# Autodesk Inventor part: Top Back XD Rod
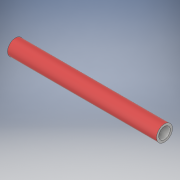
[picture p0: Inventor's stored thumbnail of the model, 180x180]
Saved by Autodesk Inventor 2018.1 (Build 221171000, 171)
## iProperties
Created: 2018-06
Part Number: Top Back XD Rod
Material: Generic
Document SubType Name: Modeling
Designer: Ryan
Density: 1 g/cm^3
Appearance: Default
Author: Ryan
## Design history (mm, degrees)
derived "Assembly3 Part out.iam"
sketch "Sketch1"
  geometry: L1 (-38.527, 77.015)-(136.232, 77.015); L2 (136.232, 77.015)-(136.232, -217.058); L3 (136.232, -217.058)-(-38.527, -217.058); L4 (-38.527, -217.058)-(-38.527, 77.015); 1 further point
  constraints: 8 end point, 2 parallel, 1 horizontal, 1 perpendicular
extrude "Extrusion1" cut sketch "Sketch1" distance "d1" = 25.4; taper "d2" = 0 deg
workplane "Work Plane2"
  workplane "Work Plane1"
workpoint "Work Point1"
workplane "Work Plane3"
workplane "Work Plane4"
workplane "Work Plane5"
workplane "Work Plane6"
workplane "Work Plane7"
workplane "Work Plane8"
workplane "Work Plane9"
workplane "Work Plane10"
workplane "Work Plane11"
workplane "Work Plane12"
sketch "Sketch2"
  geometry: L1 (227.789, 28.997)-(-104.46, 28.997); L2 (-104.46, 28.997)-(-104.46, -117.244); L3 (-104.46, -117.244)-(227.789, -117.244); L4 (227.789, -117.244)-(227.789, 28.997); 1 further point
  constraints: 8 end point, 2 parallel, 1 horizontal, 1 perpendicular
extrude "Extrusion2" cut sketch "Sketch2" distance "d10" = 169.8625; taper "d11" = 0 deg
sketch "Sketch3"
  geometry: L1 (244.466, 43.749)-(-96.122, 43.749); L2 (-96.122, 43.749)-(-96.122, -113.396); L3 (-96.122, -113.396)-(244.466, -113.396); L4 (244.466, -113.396)-(244.466, 43.749); 1 further point
  constraints: 8 end point, 2 parallel, 1 horizontal, 1 perpendicular
extrude "Extrusion3" cut sketch "Sketch3" distance "d12" = 169.8625; taper "d13" = 0 deg
sketch "Sketch4"
  geometry: L1 (228.431, 30.28)-(156.593, 30.28); L2 (156.593, 30.28)-(156.593, -87.098); L3 (156.593, -87.098)-(228.431, -87.098); L4 (228.431, -87.098)-(228.431, 30.28); L5 (-98.688, 23.865)-(-20.436, 23.865); L6 (-20.436, 23.865)-(-20.436, -58.235); L7 (-20.436, -58.235)-(-98.688, -58.235); L8 (-98.688, -58.235)-(-98.688, 23.865); 1 further point
  constraints: 16 end point, 4 parallel, 2 horizontal, 2 perpendicular
extrude "Extrusion4" cut sketch "Sketch4" distance "d14" = 169.8625; taper "d15" = 0 deg
sketch "Sketch5"
  geometry: L1 (189.305, 53.37)-(41.781, 53.37); L2 (41.781, 53.37)-(41.781, -120.451); L3 (41.781, -120.451)-(189.305, -120.451); L4 (189.305, -120.451)-(189.305, 53.37); 1 further point
  constraints: 8 end point, 2 parallel, 1 horizontal, 1 perpendicular
extrude "Extrusion5" cut sketch "Sketch5" distance "d16" = 201.6125; taper "d17" = 0 deg
sketch "Sketch6"
  geometry: C1 r 4.763 at (0, 0) reference; C2 r 3.429 at (0, 0); 1 further point
  constraints: 1 centre point, 1 coincident
  dimensions: "d18" = 6.858 diameter of C2
extrude "Extrusion6" cut sketch "Sketch6" distance "d19" = 12.7; taper "d20" = 0 deg
sketch "Sketch7"
  geometry: C1 r 3.429 at (0, 0) reference; C2 r 3.429 at (0, 0); 1 further point
  constraints: 1 centre point, 1 coincident
extrude "Extrusion7" cut sketch "Sketch7" distance "d21" = 12.7; taper "d22" = 0 deg
body "Solid1"
node "Rov v4.2.ipt:1" dims "d0" = 10
node "Motor mount.ipt:1" dims "d0" = 10
node "Motor mount.ipt:2" dims "d0" = 10
node "Motor mount_MIR2.ipt:1" dims "d0" = 10
other parameters: "d3" = 6.35, "d4" = 12.7, "d5" = -12.7, "d6" = 12.7, "d7" = -12.7, "d8" = 6.35, "d9" = -6.35
